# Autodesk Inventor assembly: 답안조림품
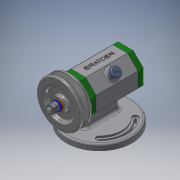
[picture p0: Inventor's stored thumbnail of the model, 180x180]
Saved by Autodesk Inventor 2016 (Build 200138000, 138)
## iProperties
Created: 2017-06
Part Number: 답안조림품
Material: 일반
Document SubType Name: Assembly
Designer: USER
Author: USER
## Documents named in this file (14)
- C:\Users\USER\Desktop\470607V1008\답안조림품.iam
- C:\Users\USER\Desktop\470607V1008\본체.ipt
- C:\Users\USER\Desktop\470607V1008\V벨트풀리.ipt
- C:\Users\USER\Desktop\470607V1008\고무캡.ipt
- C:\Users\USER\Desktop\470607V1008\너트 M 8.ipt
- C:\Users\USER\Desktop\470607V1008\뒤커버.ipt
- C:\Users\USER\Desktop\470607V1008\베어링 15 x 32 x 9.ipt
- C:\Users\USER\Desktop\470607V1008\볼트 M4 x 12.ipt
- C:\Users\USER\Desktop\470607V1008\스프링와셔 8.ipt
- C:\Users\USER\Desktop\470607V1008\앞커버.ipt
- C:\Users\USER\Desktop\470607V1008\오일 실 15 25 7.ipt
- C:\Users\USER\Desktop\470607V1008\와셔 8x17.ipt
- C:\Users\USER\Desktop\470607V1008\축.ipt
- C:\Users\USER\Desktop\470607V1008\키 3 x 3 x 12.ipt
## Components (2 placed, 2 different names)
1. V벨트풀리:1
2. 고무캡:1
